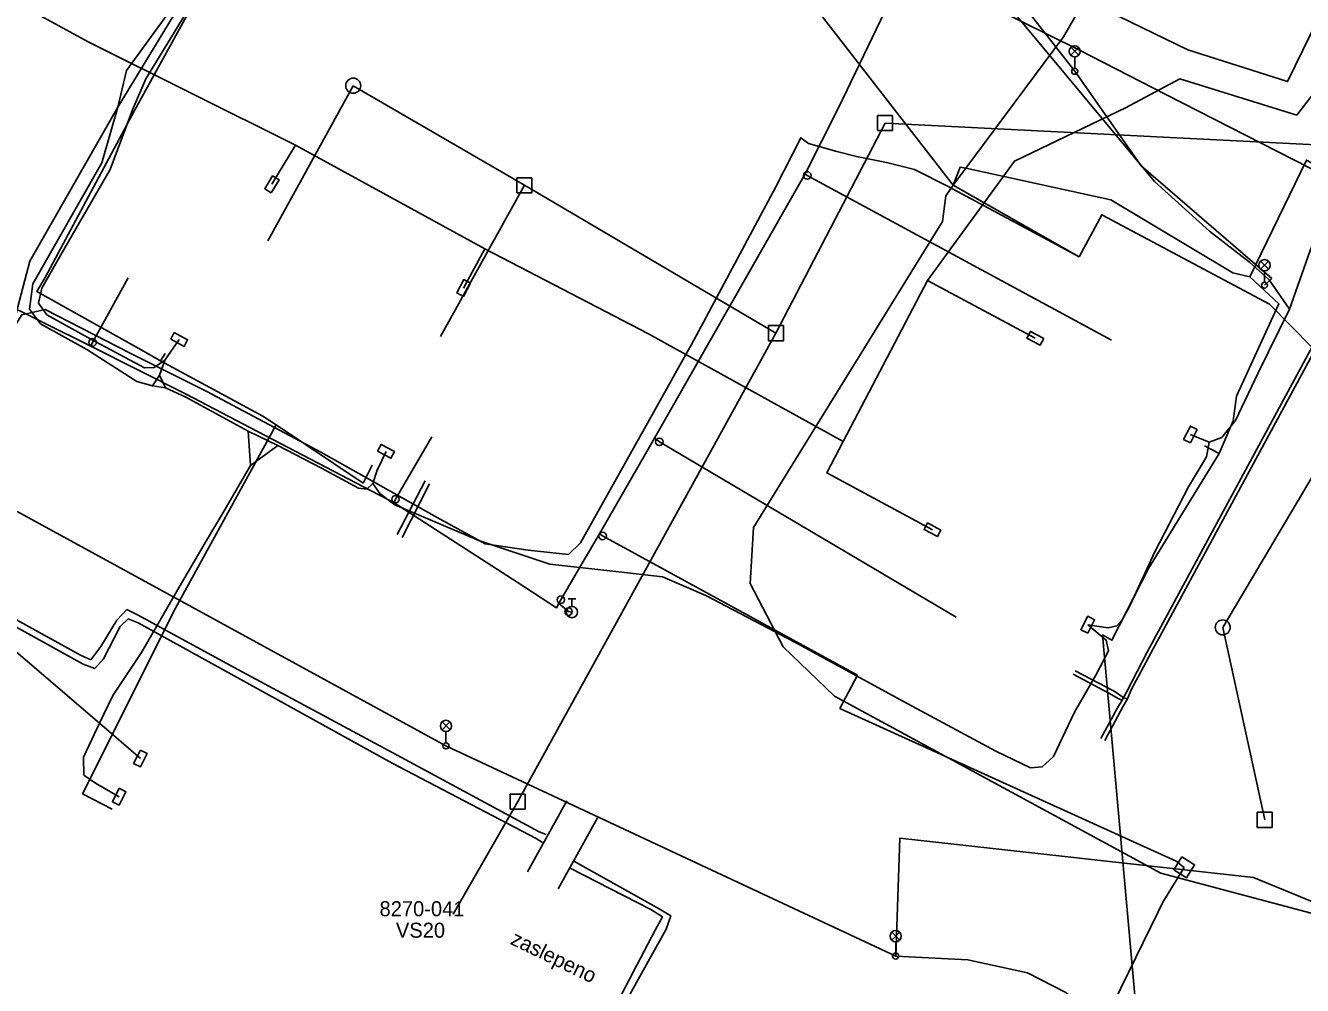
# Model space of a CAD drawing. Extents: x -736399 to -735926, y -1118992 to -1118244.
# Drawn here: x -736121.9 to -736036.9, y -1118382.8 to -1118318.9 of the extents above; entities that cross this region are included whole.
import ezdxf

# ---------------------------------------------------------------- set-up
doc = ezdxf.new("R2010")
doc.units = 0
for name, color, linetype in [('HUP', 7, 'Continuous'), ('Hydranty', 7, 'Continuous'), ('Kabelovody skutečný průběh', 7, 'Continuous'), ('Kabelové skříně NN', 7, 'Continuous'), ('Kabelové vedení NN', 7, 'Continuous'), ('Kabelové vedení VO', 7, 'Continuous'), ('Kanalizační přípojky', 7, 'Continuous'), ('Kanalizační stoka', 7, 'Continuous'), ('Kanalizační šachty', 7, 'Continuous'), ('Linie venk ved SDEL opti', 7, 'Continuous'), ('NTL plynovod', 7, 'Continuous'), ('Objekty podzemní', 7, 'Continuous'), ('Osa trasy kynety', 7, 'Continuous'), ('Podz_ teplovodní potrubí', 7, 'Continuous'), ('Popis teplovodu', 7, 'Continuous'), ('Povrchové znaky VO', 7, 'Continuous'), ('Teplovodní kanál', 7, 'Continuous'), ('Vod přípojky-voda pitná', 7, 'Continuous'), ('Vodovodní řad', 7, 'Continuous'), ('Vodovodní šoupata', 7, 'Continuous')]:
    doc.layers.add(name, color=color, linetype=linetype)

msp = doc.modelspace()

# ---------------------------------------------------------------- linework, layer by layer
at = {"layer": 'HUP'}
for points in [[(-736105.533, -1118330.057), (-736105.018, -1118329.2), (-736105.447, -1118328.943), (-736105.962, -1118329.8)], [(-736092.754, -1118336.959), (-736092.285, -1118336.076), (-736092.726, -1118335.841), (-736093.195, -1118336.724)], [(-736054.141, -1118339.754), (-736055.024, -1118339.285), (-736055.259, -1118339.726), (-736054.376, -1118340.195)], [(-736060.981, -1118352.494), (-736061.864, -1118352.025), (-736062.099, -1118352.466), (-736061.216, -1118352.935)]]:
    msp.add_lwpolyline(points, close=True, dxfattribs=at)
at = {"layer": 'Hydranty'}
for p, q in [((-736085.78, -1118357.075), (-736085.28, -1118357.075)), ((-736085.53, -1118357.575), (-736085.53, -1118357.075))]:
    msp.add_line(p, q, dxfattribs=at)
msp.add_circle((-736085.53, -1118357.95), 0.375, dxfattribs=at)
at = {"layer": 'Kabelovody skutečný průběh'}
for points in [[(-736060.16, -1118329.55), (-736099.218, -1118279.253)], [(-736060.16, -1118329.55), (-736051.79, -1118334.33)]]:
    msp.add_lwpolyline(points, dxfattribs=at)
at = {"layer": 'Kabelové skříně NN'}
for points in [[(-736112.219, -1118339.806), (-736111.336, -1118340.276), (-736111.101, -1118339.834), (-736111.984, -1118339.365)], [(-736044.385, -1118346.699), (-736043.931, -1118345.808), (-736044.376, -1118345.581), (-736044.83, -1118346.472)], [(-736098.459, -1118347.246), (-736097.576, -1118347.716), (-736097.341, -1118347.274), (-736098.224, -1118346.805)], [(-736051.215, -1118359.349), (-736050.761, -1118358.458), (-736051.206, -1118358.231), (-736051.66, -1118359.122)], [(-736114.235, -1118367.131), (-736114.689, -1118368.022), (-736114.244, -1118368.249), (-736113.79, -1118367.358)], [(-736115.646, -1118369.671), (-736116.1, -1118370.562), (-736115.654, -1118370.789), (-736115.2, -1118369.898)]]:
    msp.add_lwpolyline(points, close=True, dxfattribs=at)
at = {"layer": 'Kabelové vedení NN'}
for points in [[(-736037.78, -1118337.8), (-736039.15, -1118335.86), (-736040.45, -1118334.68), (-736043.1, -1118332.61), (-736046.76, -1118329.32), (-736052.56, -1118322.36), (-736057.34, -1118316.58), (-736059.39, -1118314.13), (-736065.02, -1118306.94), (-736069.48, -1118301.32), (-736074.21, -1118295.59), (-736077.32, -1118291.81), (-736080.91, -1118287.54), (-736082.88, -1118284.97), (-736083.6, -1118283.45), (-736083.32, -1118282.02), (-736082.98, -1118280.86), (-736081.25, -1118276.95), (-736078.98, -1118272.81), (-736077.87, -1118268.99)], [(-736112.62, -1118341.19), (-736113.32, -1118341.69), (-736113.97, -1118341.7), (-736117.54, -1118339.81), (-736120.47, -1118338.18), (-736121.01, -1118337.41), (-736120.79, -1118336.41), (-736119.26, -1118333.73), (-736116.25, -1118328.51), (-736114.77, -1118324.54), (-736113.88, -1118322.48), (-736110.52, -1118316.98), (-736106.58, -1118310.17), (-736105.54, -1118307.81)], [(-736105.54, -1118307.81), (-736107.28, -1118309.56), (-736111.25, -1118316.52), (-736115.17, -1118321.94), (-736115.74, -1118324.36)], [(-736105.54, -1118307.81), (-736106.94, -1118309.86), (-736115.74, -1118324.36)], [(-736115.74, -1118324.36), (-736121.59, -1118334.62), (-736122.62, -1118338.49), (-736128.78, -1118349.36), (-736131.54, -1118354.42)], [(-736115.74, -1118324.36), (-736116.8, -1118328.08), (-736119.87, -1118333.44), (-736121.4, -1118336.11), (-736121.63, -1118337.8), (-736120.88, -1118338.79), (-736117.8, -1118340.49), (-736114.47, -1118342.62), (-736113.44, -1118342.91)], [(-736012.76, -1118330.65), (-736012.75, -1118331.57), (-736013.67, -1118333.41), (-736015.74, -1118336.92), (-736016.6, -1118338.17), (-736017.58, -1118338.73), (-736018.73, -1118338.46), (-736025.69, -1118334.67), (-736029.82, -1118332.35), (-736033.32, -1118330.61), (-736034.91, -1118330.97), (-736035.89, -1118332.69), (-736036.41, -1118333.9), (-736037.78, -1118337.8)], [(-736043.13, -1118346.66), (-736042.3, -1118346.35), (-736041.39, -1118345.2), (-736039.87, -1118342.03), (-736037.78, -1118337.8)], [(-736112.62, -1118341.19), (-736111.66, -1118339.82)], [(-736112.96, -1118342.19), (-736112.62, -1118341.19)], [(-736113.44, -1118342.91), (-736112.96, -1118342.19)], [(-736112.57, -1118343.04), (-736113.44, -1118342.91)], [(-736112.57, -1118343.04), (-736112.96, -1118342.19)], [(-736107.08, -1118345.91), (-736111.22, -1118343.65), (-736112.57, -1118343.04)], [(-736106.92, -1118348.2), (-736107.08, -1118345.91)], [(-736105.1, -1118346.87), (-736107.08, -1118345.91)], [(-736044.38, -1118346.14), (-736043.13, -1118346.66)], [(-736106.92, -1118348.2), (-736105.1, -1118346.87)], [(-736105.1, -1118346.87), (-736102.19, -1118348.39), (-736099.73, -1118349.71), (-736099.17, -1118349.78), (-736098.78, -1118349.39)], [(-736043.13, -1118346.66), (-736043.31, -1118347.62), (-736044.5, -1118349.62), (-736046.75, -1118353.94), (-736048.41, -1118357.53), (-736048.91, -1118358.47), (-736049.28, -1118358.86), (-736049.86, -1118359), (-736051.21, -1118358.79)], [(-736098.78, -1118349.39), (-736098.49, -1118348.52), (-736097.9, -1118347.26)], [(-736116.96, -1118365.35), (-736116.07, -1118363.5), (-736114.16, -1118360.63), (-736111.67, -1118356.29), (-736109.85, -1118353.19), (-736108.66, -1118351.21), (-736106.92, -1118348.2)], [(-736051.21, -1118358.79), (-736049.98, -1118359.81), (-736049.82, -1118360.52), (-736050.67, -1118362.14), (-736052.1, -1118364.61), (-736053.5, -1118367.56), (-736054.24, -1118368.25), (-736055.03, -1118368.31), (-736057.32, -1118367.21), (-736063.47, -1118363.89), (-736070.69, -1118359.96), (-736076.63, -1118356.85), (-736079.51, -1118355.61), (-736082.4, -1118355.28), (-736087.01, -1118354.76), (-736091.73, -1118353.2), (-736097.32, -1118350.81), (-736098.3, -1118350.06), (-736098.78, -1118349.39)], [(-736131.54, -1118354.42), (-736126.73, -1118357.01), (-736116.96, -1118365.35)], [(-736115.65, -1118370.23), (-736117.23, -1118369.32), (-736118.01, -1118368.79), (-736118.03, -1118367.59), (-736116.96, -1118365.35)], [(-736116.96, -1118365.35), (-736114.24, -1118367.69)]]:
    msp.add_lwpolyline(points, dxfattribs=at)
at = {"layer": 'Kabelové vedení VO'}
for points in [[(-736052.08, -1118321.98), (-736063.96, -1118306.78)], [(-736052.08, -1118321.98), (-736047.66, -1118328.269), (-736038.963, -1118335.771), (-736039.45, -1118336.21)], [(-736093.91, -1118366.85), (-736122.45, -1118351.27)], [(-736063.99, -1118380.83), (-736093.91, -1118366.85)], [(-736063.99, -1118380.83), (-736063.71, -1118372.983), (-736040.185, -1118375.604)], [(-736040.185, -1118375.604), (-736033.175, -1118378.476), (-736008.93, -1118391.23)], [(-736055.214, -1118381.935), (-736059.179, -1118381.085), (-736063.99, -1118380.83)], [(-736047.46, -1118390.36), (-736048.474, -1118387.544), (-736050.57, -1118384.825), (-736052.722, -1118383.238), (-736055.214, -1118381.935)]]:
    msp.add_lwpolyline(points, dxfattribs=at)
at = {"layer": 'Kanalizační přípojky'}
for points in [[(-736105.77, -1118333.25), (-736100.08, -1118322.94)], [(-736094.28, -1118339.63), (-736088.69, -1118329.56)], [(-736093.43, -1118378.04), (-736089.13, -1118370.56)]]:
    msp.add_lwpolyline(points, dxfattribs=at)
at = {"layer": 'Kanalizační stoka'}
for points in [[(-736100.08, -1118322.94), (-736088.69, -1118329.56)], [(-736071.96, -1118339.4), (-736064.69, -1118325.43)], [(-736064.69, -1118325.43), (-736032.93, -1118327.02)], [(-736088.69, -1118329.56), (-736071.96, -1118339.4)], [(-736081.73, -1118357.12), (-736071.96, -1118339.4)], [(-736042.23, -1118358.97), (-736032.76, -1118343.02)], [(-736089.13, -1118370.56), (-736081.73, -1118357.12)], [(-736039.43, -1118371.77), (-736042.23, -1118358.97)]]:
    msp.add_lwpolyline(points, dxfattribs=at)
at = {"layer": 'Kanalizační šachty'}
for p, q in [((-736064.19, -1118324.93), (-736065.19, -1118324.93)), ((-736065.19, -1118324.93), (-736065.19, -1118325.93)), ((-736064.19, -1118325.93), (-736064.19, -1118324.93)), ((-736065.19, -1118325.93), (-736064.19, -1118325.93)), ((-736088.19, -1118329.06), (-736089.19, -1118329.06)), ((-736089.19, -1118329.06), (-736089.19, -1118330.06)), ((-736088.19, -1118330.06), (-736088.19, -1118329.06)), ((-736089.19, -1118330.06), (-736088.19, -1118330.06)), ((-736071.46, -1118338.9), (-736072.46, -1118338.9)), ((-736072.46, -1118338.9), (-736072.46, -1118339.9)), ((-736071.46, -1118339.9), (-736071.46, -1118338.9)), ((-736072.46, -1118339.9), (-736071.46, -1118339.9)), ((-736088.63, -1118370.06), (-736089.63, -1118370.06)), ((-736089.63, -1118370.06), (-736089.63, -1118371.06)), ((-736088.63, -1118371.06), (-736088.63, -1118370.06)), ((-736089.63, -1118371.06), (-736088.63, -1118371.06)), ((-736038.93, -1118371.27), (-736039.93, -1118371.27)), ((-736039.93, -1118371.27), (-736039.93, -1118372.27)), ((-736038.93, -1118372.27), (-736038.93, -1118371.27)), ((-736039.93, -1118372.27), (-736038.93, -1118372.27))]:
    msp.add_line(p, q, dxfattribs=at)
for centre in [(-736100.08, -1118322.94), (-736042.23, -1118358.97)]:
    msp.add_circle(centre, 0.5, dxfattribs=at)
at = {"layer": 'Linie venk ved SDEL opti'}
for points in [[(-736051.79, -1118334.33), (-736050.279, -1118331.519), (-736039.12, -1118337.47), (-736026.5, -1118350.29)], [(-736050.23, -1118359.46), (-736047.46, -1118390.36)]]:
    msp.add_lwpolyline(points, dxfattribs=at)
at = {"layer": 'NTL plynovod'}
for points in [[(-736141.66, -1118306.83), (-736138.81, -1118308.73), (-736123.33, -1118316.95), (-736117.71, -1118320.03), (-736103.92, -1118326.9), (-736091.33, -1118333.8), (-736080.44, -1118339.45), (-736067.49, -1118346.6), (-736061.88, -1118335.89), (-736056.09, -1118327.97), (-736048.69, -1118324.42), (-736045.09, -1118322.49), (-736037.3, -1118324.9), (-736034.05, -1118320.66)], [(-736103.92, -1118326.9), (-736105.49, -1118329.5)], [(-736091.33, -1118333.8), (-736092.74, -1118336.4)], [(-736061.88, -1118335.89), (-736054.7, -1118339.74)], [(-736067.49, -1118346.6), (-736068.58, -1118348.69), (-736061.54, -1118352.48)]]:
    msp.add_lwpolyline(points, dxfattribs=at)
at = {"layer": 'Objekty podzemní'}
msp.add_lwpolyline([(-736044.95, -1118374.24), (-736045.48, -1118375.09), (-736044.63, -1118375.62), (-736044.1, -1118374.77), (-736044.95, -1118374.24)], dxfattribs=at)
at = {"layer": 'Osa trasy kynety'}
for points in [[(-736059.33, -1118328.43), (-736052.82, -1118319.7), (-736051.41, -1118317.21), (-736044.56, -1118320.55), (-736037.92, -1118322.67), (-736031.35, -1118309.22), (-736026.6, -1118304.92), (-736015.96, -1118307.75), (-736010.32, -1118299.4), (-735997.45, -1118281.65), (-735994.05, -1118276.11), (-735992.63, -1118275.37), (-735991.99, -1118274.05)], [(-736099.218, -1118279.253), (-736060.16, -1118329.55)], [(-736117.16, -1118297.08), (-736117.94, -1118298.46), (-736104.49, -1118306.18), (-736114.63, -1118324.58), (-736120.58, -1118335.7), (-736121.14, -1118336.62), (-736114.35, -1118340.41)], [(-736051.79, -1118334.33), (-736060.5, -1118329.65), (-736062.73, -1118328.51), (-736064.59, -1118328.05), (-736066.59, -1118327.65), (-736067.9, -1118327.32), (-736069.78, -1118326.79), (-736070.3, -1118326.4), (-736071.96, -1118329.66), (-736077.11, -1118339.28), (-736077.58, -1118340.16), (-736078.55, -1118341.89), (-736079.04, -1118342.76), (-736084.95, -1118353.34), (-736085.76, -1118354.12), (-736088.45, -1118353.84), (-736091.31, -1118353.42), (-736094.5, -1118351.66)], [(-736059.33, -1118328.43), (-736059.7, -1118328.35), (-736060.16, -1118329.55)], [(-736060.16, -1118329.55), (-736059.33, -1118328.43)], [(-736041.55, -1118335.39), (-736049.67, -1118330.53), (-736059.33, -1118328.43)], [(-736040.42, -1118335.65), (-736036.66, -1118327.89), (-736028.9, -1118332.09), (-736017.8, -1118337.95), (-736016.27, -1118337.52), (-736012.92, -1118331.12)], [(-736060.16, -1118329.55), (-736060.66, -1118330.27), (-736060.87, -1118331.98), (-736073.44, -1118352.33), (-736073.67, -1118356.06), (-736071.48, -1118360.26), (-736068.06, -1118363.54), (-736046.35, -1118375.31), (-736036.34, -1118377.98), (-736025.99, -1118382.68), (-735984.66, -1118404.87), (-735983.92, -1118403.81), (-735979.84, -1118404.27), (-735970.81, -1118410.474), (-735958.71, -1118418.79), (-735931.65, -1118433.02), (-735927.73, -1118434.94), (-735926.489, -1118435.362)], [(-736060.16, -1118329.55), (-736051.79, -1118334.33)], [(-736040.42, -1118335.65), (-736041.55, -1118335.39)], [(-736040.42, -1118335.65), (-736038.49, -1118337.45), (-736038.64, -1118337.73), (-736041.32, -1118343.58)], [(-736094.5, -1118351.66), (-736102.24, -1118347.32), (-736109.81, -1118343.28), (-736114.93, -1118340.74), (-736120.57, -1118337.83), (-736122.14, -1118338.17), (-736128.54, -1118348.35), (-736128.87, -1118348.72)], [(-736114.35, -1118340.41), (-736112.9, -1118341.24)], [(-736112.59, -1118340.76), (-736112.9, -1118341.24)], [(-736112.9, -1118341.24), (-736106.09, -1118344.93), (-736105.2, -1118345.5)], [(-736041.32, -1118343.58), (-736041.53, -1118345.24), (-736042.46, -1118347.41)], [(-736116.11, -1118371.05), (-736118.09, -1118370.03), (-736111.91, -1118357.68), (-736105.2, -1118345.5)], [(-736098.83, -1118348.18), (-736099.43, -1118349.37), (-736105.2, -1118345.5)], [(-736042.46, -1118347.41), (-736043.45, -1118346.89)], [(-736050.23, -1118359.46), (-736049.6, -1118359.82), (-736047.16, -1118355.06), (-736042.46, -1118347.41)]]:
    msp.add_lwpolyline(points, dxfattribs=at)
at = {"layer": 'Podz_ teplovodní potrubí'}
for p, q in [((-736118.23, -1118360.82), (-736128.77, -1118355.02)), ((-736118.04, -1118361.41), (-736128.58, -1118355.62)), ((-736115.14, -1118357.79), (-736115.81, -1118358.5)), ((-736114.43, -1118358.14), (-736115.14, -1118357.79)), ((-736107.75, -1118361.78), (-736114.43, -1118358.14)), ((-736115.81, -1118358.5), (-736116.87, -1118360.23)), ((-736115.58, -1118358.9), (-736116.7, -1118361.05)), ((-736116.87, -1118360.23), (-736117.53, -1118361.13)), ((-736117.53, -1118361.13), (-736118.23, -1118360.82)), ((-736117.27, -1118361.7), (-736118.04, -1118361.41)), ((-736116.7, -1118361.05), (-736117.27, -1118361.7)), ((-736097.15, -1118367.46), (-736107.75, -1118361.78)), ((-736087.7, -1118372.57), (-736097.15, -1118367.46)), ((-736087.24, -1118372.75), (-736087.7, -1118372.57))]:
    msp.add_line(p, q, dxfattribs=at)
for points in [[(-736033.44, -1118335.06), (-736047.24, -1118360.58)], [(-736047.01, -1118360.68), (-736033.19, -1118335.16)], [(-736097.15, -1118352.8), (-736095.3, -1118349.23)], [(-736096.83, -1118353), (-736095.01, -1118349.43)], [(-736087.49, -1118373.27), (-736087.91, -1118373.02), (-736097.49, -1118368.01), (-736108, -1118362.19), (-736114.38, -1118358.67), (-736115.05, -1118358.41), (-736115.58, -1118358.9)], [(-736048.93, -1118363.82), (-736048.62, -1118363.23), (-736047.24, -1118360.58)], [(-736047.01, -1118360.68), (-736048.32, -1118363.13)], [(-736052.18, -1118362.08), (-736049.8, -1118363.34)], [(-736052.04, -1118361.85), (-736049.45, -1118363.22)], [(-736049.8, -1118363.34), (-736049.15, -1118363.73), (-736048.93, -1118363.82)], [(-736049.45, -1118363.22), (-736048.8, -1118363.66), (-736048.57, -1118363.72)], [(-736048.57, -1118363.72), (-736048.32, -1118363.13)], [(-736050.08, -1118366.5), (-736048.86, -1118364.21)], [(-736048.93, -1118363.82), (-736049.24, -1118364.33)], [(-736048.57, -1118363.72), (-736048.86, -1118364.21)], [(-736049.24, -1118364.33), (-736050.35, -1118366.35)], [(-736120.04, -1118411.3), (-736119.98, -1118410.45), (-736119.14, -1118410.27), (-736107.14, -1118409.69), (-736106.27, -1118409.64), (-736094.1, -1118408.95), (-736089.01, -1118397.88), (-736083.91, -1118386.61), (-736080, -1118379.1), (-736079.51, -1118378.22), (-736080.29, -1118377.73), (-736085.7, -1118374.96)], [(-736085.36, -1118374.54), (-736079.73, -1118377.69), (-736078.95, -1118378.15), (-736079.27, -1118379.05), (-736083.65, -1118386.93), (-736088.58, -1118398.3), (-736093.63, -1118409.39), (-736105.74, -1118410.06), (-736106.67, -1118410.13), (-736118.68, -1118410.62), (-736119.59, -1118410.8), (-736119.57, -1118411.58)]]:
    msp.add_lwpolyline(points, dxfattribs=at)
at = {"layer": 'Povrchové znaky VO'}
for p, q in [((-736052.344, -1118320.918), (-736051.816, -1118320.39)), ((-736051.808, -1118320.915), (-736052.336, -1118320.386)), ((-736052.08, -1118321.03), (-736052.08, -1118321.78)), ((-736039.714, -1118335.148), (-736039.186, -1118334.62)), ((-736039.178, -1118335.145), (-736039.706, -1118334.616)), ((-736039.45, -1118335.26), (-736039.45, -1118336.01)), ((-736094.174, -1118365.788), (-736093.646, -1118365.26)), ((-736093.638, -1118365.785), (-736094.166, -1118365.256)), ((-736093.91, -1118365.9), (-736093.91, -1118366.65)), ((-736064.254, -1118379.768), (-736063.726, -1118379.24)), ((-736063.718, -1118379.765), (-736064.246, -1118379.236)), ((-736063.99, -1118379.88), (-736063.99, -1118380.63))]:
    msp.add_line(p, q, dxfattribs=at)
for centre, radius in [((-736052.08, -1118320.655), 0.375), ((-736052.08, -1118321.98), 0.2), ((-736039.45, -1118334.885), 0.375), ((-736039.45, -1118336.21), 0.2), ((-736093.91, -1118365.525), 0.375), ((-736093.91, -1118366.85), 0.2), ((-736063.99, -1118379.505), 0.375), ((-736063.99, -1118380.83), 0.2)]:
    msp.add_circle(centre, radius, dxfattribs=at)
at = {"layer": 'Teplovodní kanál'}
for p, q in [((-736088.476, -1118375.233), (-736085.87, -1118370.51)), ((-736086.44, -1118376.356), (-736083.834, -1118371.633))]:
    msp.add_line(p, q, dxfattribs=at)
at = {"layer": 'Vod přípojky-voda pitná'}
for points in [[(-736070.02, -1118328.81), (-736069.87, -1118328.91), (-736049.62, -1118339.86)], [(-736117.54, -1118340.27), (-736117.42, -1118340.01), (-736115.06, -1118335.73)], [(-736097.36, -1118350.68), (-736097.27, -1118350.44), (-736094.85, -1118346.29)], [(-736080.03, -1118346.39), (-736079.71, -1118346.63), (-736059.97, -1118358.28)]]:
    msp.add_lwpolyline(points, dxfattribs=at)
at = {"layer": 'Vodovodní řad'}
for points in [[(-736083.7, -1118352.75), (-736080.03, -1118346.39), (-736070.02, -1118328.81), (-736067.78, -1118324.36), (-736064.17, -1118316.88), (-736063.21, -1118314.91), (-736051.81, -1118320.55), (-736046.02, -1118323.52), (-736031.15, -1118331.1)], [(-736105.93, -1118346.2), (-736111.23, -1118343.43), (-736117.54, -1118340.27), (-736133.54, -1118332.33), (-736135.72, -1118331.28)], [(-736086.39, -1118357.37), (-736086.55, -1118357.66), (-736089.17, -1118355.97), (-736097.36, -1118350.68), (-736105.93, -1118346.2)], [(-736083.7, -1118352.75), (-736085.1, -1118355.13)], [(-736083.49, -1118352.89), (-736083.7, -1118352.75)], [(-736044.79, -1118374.93), (-736045.33, -1118374.52), (-736067.7, -1118364.36), (-736066.54, -1118362.15), (-736083.49, -1118352.89)], [(-736085.1, -1118355.13), (-736086.27, -1118357.13)], [(-736086.27, -1118357.13), (-736086.39, -1118357.37)], [(-736086.39, -1118357.37), (-736085.76, -1118357.92)], [(-736085.76, -1118357.92), (-736085.53, -1118357.95)], [(-736046.53, -1118377.88), (-736046.22, -1118377.25), (-736044.79, -1118374.93)], [(-736051.09, -1118410.02), (-736049.27, -1118394.87), (-736049.57, -1118390.45), (-736050.49, -1118386.01), (-736046.53, -1118377.88)]]:
    msp.add_lwpolyline(points, dxfattribs=at)
at = {"layer": 'Vodovodní šoupata'}
for centre in [(-736069.87, -1118328.91), (-736117.42, -1118340.01), (-736079.71, -1118346.63), (-736097.27, -1118350.44), (-736083.49, -1118352.89), (-736086.27, -1118357.13), (-736085.76, -1118357.92)]:
    msp.add_circle(centre, 0.25, dxfattribs=at)

# ---------------------------------------------------------------- texts
at = {"layer": 'Popis teplovodu'}
for s, p in [('8270-041', (-736098.33, -1118378.18)), ('VS20', (-736097.24, -1118379.61))]:
    msp.add_text(s, height=1, dxfattribs=at).set_placement(p)
msp.add_text('zaslepeno', height=1, rotation=334.16026, dxfattribs=at).set_placement((-736089.693, -1118380.005))

doc.saveas('drawing.dxf')
